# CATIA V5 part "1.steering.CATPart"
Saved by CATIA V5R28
Part number: steering
Bounding box of the stored display mesh (mm): x -46.838 to 107.133, y -277.4 to 277.4, z -449.975 to 181.531
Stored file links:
  D:\Catia Cycle design\1.steering.CATPart
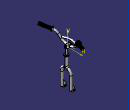
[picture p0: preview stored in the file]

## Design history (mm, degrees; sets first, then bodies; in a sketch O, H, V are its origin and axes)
Set1
  Sketch1 on xy-plane, origin (0, 0, 0), H (1, 0, 0), V (0, 1, 0)
    point P1 (-35, 0)
    line L1 (-35, 0) -> (-35, 14)
    point P2 (-35, 20)
    line L2 (-29, 20) -> (4.4421, 20)
    point P3 (10, 20)
    line L3 (15.0721, 17.7277) -> (30.2708, 10.9187)
    point P4 (35, 8.8)
    line L4 (35, 3.6179) -> (35, 0)
    point P5 (35, 0)
    point P6 (-35, -20)
    point P7 (-35, 0)
    line L5 (-35, 0) -> (-35, -14)
    point P8 (10, -20)
    line L6 (-29, -20) -> (4.4421, -20)
    point P9 (35, -8.8)
    line L7 (15.0721, -17.7277) -> (30.2708, -10.9187)
    point P10 (35, 0)
    line L8 (35, -3.6179) -> (35, 0)
    arc A1 centre (4.4421, -6) radius 26 from (4.4421, 20) to (15.0721, 17.7277) cw
    arc A2 centre (4.4421, 6) radius 26 from (4.4421, -20) to (15.0721, -17.7277) ccw
    arc A3 centre (27, 3.6179) radius 8 from (30.2708, 10.9187) to (35, 3.6179) cw
    arc A4 centre (27, -3.6179) radius 8 from (30.2708, -10.9187) to (35, -3.6179) ccw
    arc A5 centre (-29, -14) radius 6 from (-35, -14) to (-29, -20) ccw
    arc A6 centre (-29, 14) radius 6 from (-35, 14) to (-29, 20) cw
    distance L2 L6 = 40
    distance P4 P9 = 17.6
    distance L4 L1 = 70
    distance V L1 = 35
    distance P2 P3 = 45
    radius A1 = 26
    radius A2 = 26
    radius A3 = 8
    radius A4 = 8
    radius A5 = 6
    radius A6 = 6
    coincidence: P1 H, P5 H, L2 P3, L3 P3, L6 P8, L7 P8, L3 P4, L4 P4, L7 P9, L8 P9, L5 P6, L6 P6, L1 P2, L2 P2, P1 P7, P5 P10
    vertical: L1 V, L4 V
    horizontal: L2 H
    symmetry: P2 P6 H, P1 P7 H, L1 L5 H, P3 P8 H, L2 L6 H, P4 P9 H, L3 L7 H, P5 P10 H, L4 L8 H
    tangency: A1 L2, A1 L3, A2 L6, A2 L7, A3 L3, A3 L4, A4 L7, A4 L8, A5 L5, A5 L6, A6 L1, A6 L2
  Plane1: type Offset, RefPlane yz-plane, Offset 20
  Plane2: type Offset, RefPlane zx-plane, Offset 50
  Point1: type Center, Curve Sketch8
  Point2: (0, 67, 0), relative to Point1
  Point3: (29, 57, 107.5), relative to Point2
  Point4: (103.5, 200, 150), relative to Point2
  Line1: type PtPt, FirstPoint Point1, SecondPoint Point2
  Line2: type PtPt, FirstPoint Point2, SecondPoint Point3
  Line3: type PtPt, FirstPoint Point3, SecondPoint Point4
  Corner1: Element1 Line2, Element2 Line1, Radius 72
  Corner2: Element1 Line3, Element2 Corner1, Radius 72
  Point5: type Center, Curve Sketch11
  Plane3: type OffsetPt, RefPlane xy-plane, RefPoint Point5
Body1 (main body)
  Pad1: profile Sketch1, direction (0, 0, 1), length 10, mirrored extent
  Sketch2 on zx-plane, origin (0, 0, 0), H (-1, 0, 0), V (0, 0, 1)
    point P1 (3.4988, 5.9112)
    construction line L1 (35, 10) -> (23.9, 10)
    point P2 (35, 10)
    point P3 (-35, 10)
    reference projected line E1 (-35, -10) -> (-35, 10) from edge [face of Pad1 from Sketch1.L8 | face of Pad1 from Sketch1.A4]
    reference projected line E2 (35, -10) -> (35, 10) from edge [face of Pad1 from Sketch1.A5 | face of Pad1 from Sketch1.L5]
    arc A1 centre (12.3377, 14.75) radius 12.5 from (23.9, 10) to (0.7753, 10) cw
    point P4 (12.3377, 14.75)
    point P5 (23.9, 10)
    point P6 (0.7753, 10)
    reference projected line E3 (35, -10) -> (35, 10) from edge [face of Pad1 from Sketch1.A5 | face of Pad1 from Sketch1.L5]
    construction line L2 (0.7753, 10) -> (-35, 10)
    line L3 (35, 6) -> (26.3265, 6)
    point P7 (35, 6)
    arc A2 centre (12.3377, 14.75) radius 16.5 from (-1.6512, 6) to (26.3265, 6) ccw
    line L4 (-1.6512, 6) -> (-35, 6)
    point P10 (-35, 6)
    curve C1
    line L5 (23.9, 10) -> (0.7753, 10)
    reference projected line E4 (35, -10) -> (35, 10) from edge [face of Pad1 from Sketch1.A5 | face of Pad1 from Sketch1.L5]
    reference projected line E5 (-35, -10) -> (-35, 10) from edge [face of Pad1 from Sketch1.L8 | face of Pad1 from Sketch1.A4]
    reference projected line E6 (29, 10) -> (-4.4421, 10) from edge [face of Pad1 from Sketch1.L6 | end face of Pad1]
    line L6 (35, 6) -> (35, -20)
    line L7 (35, -20) -> (-35, -20)
    line L8 (-35, -20) -> (-35, 6)
    distance P4 L1 = 4.75
    radius A1 = 12.5
    distance P5 E3 = 11.1
    horizontal: L1 H, L2 H, L5 H, L7 H
    coincidence: P3 E1, P2 E2, P6 L1, A1 P1, L1 L2, P7 E4, P10 E5, L5 E6
    vertical: L6 V, L8 V
  Pocket1: profile Sketch2, direction (0, -1, 0), length 25, mirrored extent
  Sketch3 on face of Pocket1 from Sketch2.L4, origin (0, 0, 6), H (1, 0, 0), V (0, -1, 0)
    circle A1 centre (20, 0) radius 10
    point P1 (20, 0)
    radius A1 = 10
    distance P1 V = 20
    coincidence: P1 H
  Pad2: profile Sketch3, direction (0, 0, -1), length 75
  Sketch4 on end face of Pad2, origin (0, 0, -69), H (1, 0, 0), V (0, -1, 0)
    circle A1 centre (20, 0) radius 15
    point P1 (20, 0)
    radius A1 = 15
    coincidence: P1 H
  Pad3: profile Sketch4, direction (0, 0, -1), length 150
  Sketch5 on zx-plane, origin (0, 0, 0), H (-1, 0, 0), V (0, 0, 1)
    circle A1 centre (-20, -189) radius 15
    point P1 (-20, -189)
    reference projected point E1 (-20, -189) from Sketch6.P3
    radius A1 = 15
    coincidence: P1 E1
  Sketch6 on Plane1, origin (20, 0, 0), H (0, 1, 0), V (0, 0, 1)
    axis line L1 (0, -160) -> (0, -270)
    point P1 (0, -160)
    point P3 (0, -189)
    line L2 (0, -189) -> (-24.7473, -204)
    point P4 (-24.7473, -204)
    arc A1 centre (10.5, -262.1518) radius 68 from (-24.7473, -204) to (-57.5, -262.1518) ccw
    point P6 (-57.5, -262.1518)
    line L3 (-57.5, -262.1518) -> (-57.5, -419)
    point P7 (-57.5, -419)
    reference projected line E1 (15, -219) -> (-15, -219) from edge [face of Pad3 from Sketch4.A1 | end face of Pad3]
    reference projected line E2 (15, -219) -> (-15, -219) from edge [face of Pad3 from Sketch4.A1 | end face of Pad3]
    radius A1 = 68
    distance P3 P7 V = 230
    distance P6 L1 = 57.5
    distance P4 E1 = 15
    distance P3 E2 = 30
    coincidence: P1 V, P3 L1
    vertical: L1 V, L3 V
    tangency: A1 L2, A1 L3
  Rib1: profile Sketch5, centre curve Sketch6
  Mirror1: of Rib1, about zx-plane
  Sketch7 on Plane2, origin (0, 50, 0), H (-1, 0, 0), V (0, 0, 1)
    construction line L1 (-20, 60) -> (-20, -590)
    axis line L2 (-35, -419) -> (-5, -419)
    point P3 (-35, -419)
    point P4 (-5, -419)
    reference projected curve E1 from edge [face of Mirror1 | face of Mirror1]
    reference projected curve E2 from edge [face of Mirror1 | face of Mirror1]
    point P5 (-10, -359.9749)
    line L3 (-10, -359.9749) -> (-1.7591, -365.8168)
    line L4 (1.118, -368.9749) -> (25.9808, -412.0385)
    point P6 (30, -419)
    line L5 (30, -427.0385) -> (30, -445.9749)
    point P7 (30, -449.9749)
    line L6 (26, -449.9749) -> (24, -449.9749)
    point P8 (20, -449.9749)
    line L7 (20, -445.9749) -> (20, -424.9749)
    arc A1 centre (15, -424.9749) radius 5 from (20, -424.9749) to (10, -424.9749) ccw
    point P10 (15, -424.9749)
    line L8 (10, -424.9749) -> (10, -445.9749)
    point P12 (10, -449.9749)
    line L9 (6, -449.9749) -> (2.504, -449.9749)
    point P13 (0, -449.9749)
    line L10 (-1.094, -447.7225) -> (-17, -414.9749)
    point P14 (-17, -414.9749)
    line L11 (-17, -414.9749) -> (-10, -411.7107)
    line L12 (-10, -411.7107) -> (-10, -359.9749)
    reference projected curve E3 from edge [face of Rib1 | face of Rib1]
    arc A2 centre (-7.5423, -373.9749) radius 10 from (1.118, -368.9749) to (-1.7591, -365.8168) ccw
    point P16 (1.118, -368.9749)
    arc A3 centre (0, -427.0385) radius 30 from (25.9808, -412.0385) to (30, -427.0385) cw
    arc A4 centre (26, -445.9749) radius 4 from (30, -445.9749) to (26, -449.9749) cw
    arc A5 centre (24, -445.9749) radius 4 from (20, -445.9749) to (24, -449.9749) ccw
    arc A6 centre (6, -445.9749) radius 4 from (10, -445.9749) to (6, -449.9749) cw
    arc A7 centre (2.504, -445.9749) radius 4 from (2.504, -449.9749) to (-1.094, -447.7225) cw
    distance L1 V = 20
    length L2 = 30
    radius A1 = 5
    distance P5 L9 = 90
    distance P10 L9 = 25
    distance E3 L9 = 38.75
    angle L12 L11 = 115
    distance P14 L1 = 3
    radius A2 = 10
    distance P16 L9 = 81
    angle L12 L4 = 30
    radius A3 = 30
    distance P7 P8 = 10
    radius A4 = 4
    radius A5 = 4
    distance P12 P13 = 10
    radius A6 = 4
    radius A7 = 4
    distance L12 L1 = 10
    distance P14 L9 = 35
    vertical: L1 V, L7 V, L12 V, L5 V, L8 V
    coincidence: E1 P4, P3 E2, P12 L6, P13 V, P6 L2, L4 P6, L5 P6, L5 P7, L6 P7, L7 P8, L6 P8, L8 P12, L9 P12, L9 P13, L10 P13
    horizontal: L2 H, L6 H, L9 H
    tangency: A1 L7, L8 A1, A2 L4, A2 L3, A3 L4, A3 L5, A4 L5, A4 L6, A5 L7, A5 L6, A6 L8, A6 L9, A7 L9, A7 L10
  Pad4: profile Sketch7, direction (0, 1, 0), length 4
  Mirror2: of Pad4, about zx-plane
  Sketch8 on zx-plane, origin (0, 0, 0), H (-1, 0, 0), V (0, 0, 1)
    circle A1 centre (12.3377, 14.75) radius 12.5
    reference projected arc E1 centre (12.3377, 14.75) radius 12.5 from (0.7753, 10) to (23.9, 10) ccw from edge [face of Pocket1 from Sketch2.A1 | face of Pad1 from Sketch1.L2]
    coincidence: A1 E1
  Sketch9 on yz-plane, origin (0, 0, 0), H (0, 1, 0), V (0, 0, 1)
  Sketch10 on end face of Pad2, origin (0, 0, -69), H (1, 0, 0), V (0, -1, 0)
  Rib2: profile Sketch8, centre curve Corner2
  Mirror3: of Rib2, about zx-plane
  Sketch11 on zx-plane, origin (0, 0, 0), H (-1, 0, 0), V (0, 0, 1)
    circle A1 centre (37.3377, 60) radius 9.5
    point P1 (37.3377, 60)
    reference projected point E1 (12.3377, 14.75) from Point1
    radius A1 = 9.5
    distance P1 H = 60
    distance E1 P1 H = 25
  Sketch12 on Plane3, origin (0, 0, 60), H (1, 0, 0), V (0, 1, 0)
    arc A1 centre (102.6623, 0) radius 140 from (0, 95.1864) to (0, -95.1864) ccw
    point P2 (0, -95.1864)
    point P3 (0, 95.1864)
    reference projected point E1 (-37.3377, 0) from Point5
    radius A1 = 140
    coincidence: P2 V, E1 A1, P3 V
    symmetry: P3 P2 H
  Rib3: profile Sketch11, centre curve Sketch12
Body2
  Sketch13 on face of Mirror3, origin (139.2565, -267.2978, 79.4417), H (0.8869, 0.462, 0), V (-0.1178, 0.226, 0.967)
    circle A1 centre (-42.5153, 88.2219) radius 15.85
    reference projected circle E1 centre (-42.5153, 88.2219) radius 12.5 from edge [face of Mirror3 | face of Mirror3]
    projected circle E2 centre (-42.5153, 88.2219) radius 12.5 from edge [face of Mirror3 | face of Mirror3]
    radius A1 = 15.85
    concentricity: A1 E1
  Pad5: profile Sketch13, direction (-0.4468, 0.8576, -0.2549), length 123
  Sketch14 on end face of Pad5, origin (84.303, -161.8164, 48.0923), H (-0.8869, -0.462, 0), V (-0.1178, 0.226, 0.967)
    circle A1 centre (42.5153, 88.2219) radius 30
    reference projected circle E1 centre (42.5153, 88.2219) radius 12.5 from edge [face of Mirror3 | face of Mirror3]
    radius A1 = 30
    concentricity: A1 E1
  Pad6: profile Sketch14, direction (-0.4468, 0.8576, -0.2549), length 4
  Sketch15 on start face of Pad5, origin (139.2565, -267.2978, 79.4417), H (0.8869, 0.462, 0), V (-0.1178, 0.226, 0.967)
    circle A1 centre (-42.5153, 88.2219) radius 17
    reference projected circle E1 centre (-42.5153, 88.2219) radius 15.85 from edge [face of Pad5 from Sketch13.A1 | start face of Pad5]
    radius A1 = 17
    concentricity: A1 E1
  Pad7: profile Sketch15, direction (0.4468, -0.8576, 0.2549), length 2
  Fillet1: radius 4, on edge [start face of Pad6 | face of Pad5 from Sketch13.A1]
  Fillet2: radius 2, on edge [start face of Pad6 | face of Pad6 from Sketch14.A1]
  Fillet3: radius 2, on edge [face of Pad6 from Sketch14.A1 | end face of Pad6]
  Fillet4: radius 1, on edge [face of Pad5 from Sketch13.A1 | start face of Pad7]
  Sketch16 on end face of Pad7, origin (140.1501, -269.0129, 79.9514), H (0.8869, 0.462, 0), V (-0.1178, 0.226, 0.967)
    circle A1 centre (-42.744, 105.2204) radius 2.5
    point P1 (-42.744, 105.2204)
    reference projected circle E1 centre (-42.5153, 88.2219) radius 17 from edge [face of Pad7 from Sketch15.A1 | end face of Pad7]
    radius A1 = 2.5
    coincidence: P1 E1
  Pocket2: profile Sketch16, direction (-0.4468, 0.8576, -0.2549), length 120, opposite side length -3
  CircPattern1: of Pocket2, instances 10, angular step 36 {= 360.0*1 deg/CircPattern1.AngularNumber}, axis from end face of Pad7
  Mirror4: of the body so far, about zx-plane
Body3
  Sketch17 on end face of Pad1, origin (0, 0, 10), H (1, 0, 0), V (0, 1, 0)
  Pad8: profile Sketch17, direction (0, 0, 1), length 4
  Sketch18 on zx-plane, origin (0, 0, 0), H (-1, 0, 0), V (0, 0, 1)
    projected circle E1 centre (12.3377, 14.75) radius 12.5 from Sketch8.A1
    projected arc E2 centre (12.3377, 14.75) radius 12.5 from (24.8151, 14) to (-0.1398, 14) ccw from Sketch8.A1
    line L1 (-35, 29) -> (35, 29)
    line L2 (35, 29) -> (35, 14)
    line L3 (35, 14) -> (24.8151, 14)
    line L4 (-35, 14) -> (-35, 29)
    reference projected line E3 (35, 10) -> (35, 14) from edge [face of Pad8 | face of Pad8]
    reference projected line E4 (-35, 10) -> (-35, 14) from edge [face of Pad8 | face of Pad8]
    reference projected line E5 (-15.0721, 14) -> (-4.4421, 14) from edge [face of Pad8 | end face of Pad8]
    point P5 (24.8151, 14)
    line L5 (-0.1398, 14) -> (-35, 14)
    point P6 (-0.1398, 14)
    length L2 = 15
    horizontal: L1 H, L3 H, L5 H
    vertical: L2 V, L4 V
    coincidence: L2 E3, L4 E4, L3 E5, E1 P5, E1 P6, L3 L5
  Pad9: profile Sketch18, direction (0, 1, 0), length 20, mirrored extent
  Fillet5: radius 6, on edge [face of Pad9 | face of Pad9] (x2)
  Sketch19 on face of Pad9 from Sketch18.L5, origin (0, 0, 14), H (1, 0, 0), V (0, -1, 0)
  Pocket3: profile Sketch19, direction (0, 0, 1), through (limit type 3)
  Sketch20 on start face of Pad3, origin (0, 0, -69), H (1, 0, 0), V (0, 1, 0)
    point P1 (20, 0)
    point P2 (40, 0)
    construction circle A1 centre (20, 0) radius 23.094
    construction circle A2 centre (20, 0) radius 20
    point P3 (40, -11.547)
    point P4 (40, 11.547)
    point P5 (20, 23.094)
    point P6 (0, 11.547)
    point P7 (0, -11.547)
    point P8 (20, -23.094)
    line L1 (40, -11.547) -> (40, 11.547)
    line L2 (40, 11.547) -> (20, 23.094)
    line L3 (20, 23.094) -> (0, 11.547)
    line L4 (0, 11.547) -> (0, -11.547)
    line L5 (0, -11.547) -> (20, -23.094)
    line L6 (20, -23.094) -> (40, -11.547)
    construction line L7 (20, 0) -> (40, 0)
    reference projected circle E1 centre (20, 0) radius 15 from edge [start face of Pad3 | face of Pad3 from Sketch4.A1]
    projected circle E2 centre (20, 0) radius 10 from edge [face of Pad2 from Sketch3.A1 | start face of Pad3]
    distance L6 L3 = 40
    coincidence: A1 P3, A1 P4, A1 P5, A1 P6, A1 P7, A1 P8, P2 H
    tangency: A2 L1, A2 L2, A2 L3, A2 L4, A2 L5, A2 L6
    midpoint: P2 L1
    concentricity: P1 E1
  Pad10: profile Sketch20, direction (0, 0, 1), length 5
  Sketch21 on start face of Pad10, origin (0, 0, -69), H (1, 0, 0), V (0, -1, 0)
    circle A1 centre (20, 0) radius 25
    point P1 (20, 0)
    point P2 (45, 0)
    reference projected circle E1 centre (20, 0) radius 15 from edge [start face of Pad3 | face of Pad3 from Sketch4.A1]
    radius A1 = 25
    coincidence: A1 P2, P2 H
    concentricity: P1 E1
  Pad11: profile Sketch21, direction (0, 0, -1), length 5
  Sketch22 on face of Pad9 from Sketch18.L1, origin (0, 0, 29), H (1, 0, 0), V (0, 1, 0)
    circle A1 centre (23, 0) radius 6
    point P1 (23, 0)
    radius A1 = 6
    distance P1 V = 23
    coincidence: P1 H
  Pocket4: profile Sketch22, direction (0, 0, -1), through (limit type 3), offset 20
  Sketch23 on face of Pad9 from Sketch18.L1, origin (0, 0, 29), H (1, 0, 0), V (0, 1, 0)
    line L1 (-28, 13) -> (-2, 13)
    line L2 (-2, 13) -> (-2, -13)
    line L3 (-2, -13) -> (-28, -13)
    line L4 (-28, -13) -> (-28, 13)
    reference projected line E1 (-35, 20) -> (35, 20) from edge [face of Pad9 from Sketch18.L1 | face of Pad9]
    reference projected line E2 (-35, -20) -> (-35, 20) from edge [face of Pad9 from Sketch18.L1 | face of Pad9]
    distance L1 E1 = 7
    distance L2 V = 2
    distance E2 L4 = 7
    horizontal: L1 H, L3 H
    vertical: L2 V, L4 V
    symmetry: L1 L3 H
  Pocket5: profile Sketch23, direction (0, 0, -1), length 1.5
  Fillet6: radius 5, on edge [face of Pocket5 from Sketch23.L1 | face of Pocket5 from Sketch23.L2]; edge [face of Pocket5 from Sketch23.L2 | face of Pocket5 from Sketch23.L3]; edge [face of Pocket5 from Sketch23.L3 | face of Pocket5 from Sketch23.L4]; edge [face of Pocket5 from Sketch23.L4 | face of Pocket5 from Sketch23.L1]
  Sketch24 on face of Pad9 from Sketch18.L1, origin (0, 0, 29), H (1, 0, 0), V (0, 1, 0)
    point P1 (23, 0)
    point P2 (23, 7.5001)
    construction circle A1 centre (23, 0) radius 8.6603
    construction circle A2 centre (23, 0) radius 7.5
    point P3 (27.3301, 7.5)
    point P4 (18.6699, 7.5)
    point P5 (14.3397, 0)
    point P6 (18.6699, -7.5)
    point P7 (27.3301, -7.5)
    point P8 (31.6603, 0)
    line L1 (27.3301, 7.5) -> (18.6699, 7.5)
    line L2 (18.6699, 7.5) -> (14.3397, 0)
    line L3 (14.3397, 0) -> (18.6699, -7.5)
    line L4 (18.6699, -7.5) -> (27.3301, -7.5)
    line L5 (27.3301, -7.5) -> (31.6603, 0)
    line L6 (31.6603, 0) -> (27.3301, 7.5)
    construction line L7 (23, 0) -> (23, 7.5001)
    reference projected circle E1 centre (23, 0) radius 6 from edge [face of Pad9 from Sketch18.L1 | face of Pocket4 from Sketch22.A1]
    distance L2 L5 = 15
    coincidence: A1 P3, A1 P4, A1 P5, A1 P6, A1 P7, A1 P8, P1 H
    tangency: A2 L1, A2 L2, A2 L3, A2 L4, A2 L5, A2 L6
    midpoint: P2 L1
    concentricity: P1 E1
    parallelism: L6 L3
    vertical: L7 V
  Pad12: profile Sketch24, direction (0, 0, 1), length 4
